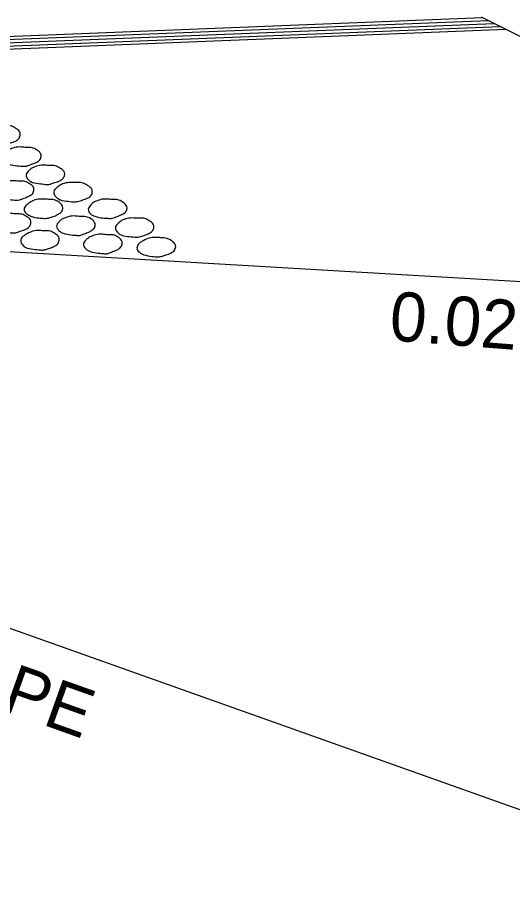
# Model space of a CAD drawing. Extents: x 438659 to 573674, y 10724 to 98600.
# Drawn here: x 514843 to 516659, y 68148 to 71311 of the extents above; entities that cross this region are included whole.
import ezdxf

# ---------------------------------------------------------------- set-up
doc = ezdxf.new("R2010")
doc.units = 0
doc.layers.add('T_Vehicle Path Rt', color=7, linetype='Continuous')

msp = doc.modelspace()

# ---------------------------------------------------------------- linework, layer by layer
at = {"layer": 'T_Vehicle Path Rt'}
for p, q in [((497292.2, 70531), (516568.3, 71300)), ((497314.8, 70541.7), (516547.7, 71310.2)), ((520270.3, 69449), (516544.6, 71311.4)), ((497241.8, 70505.8), (516612.3, 71278.1)), ((497266.8, 70517.7), (516590.9, 71289)), ((497216.5, 70492.7), (516634.1, 71267.2)), ((514103.7, 70495.3), (518717.5, 70225)), ((512200.6, 70004), (517415.7, 68148.2))]:
    msp.add_line(p, q, dxfattribs=at)
for points in [[(514783.6, 70844.5), (514758.1, 70847.7), (514730.2, 70855.4), (514714.2, 70869.7), (514712, 70877), (514720.3, 70894), (514729.3, 70900.3), (514745, 70910.3), (514768.6, 70915.1), (514780.5, 70915.1), (514799.4, 70915.8), (514820.3, 70913.2), (514837.5, 70904.4), (514851.3, 70892.8), (514853.8, 70882.6), (514849.1, 70869), (514838.7, 70858.8), (514826.3, 70853.7), (514809.6, 70849.4), (514799.4, 70846.4), (514783.6, 70844.5)], [(514860.8, 70765.9), (514834.6, 70768.3), (514805.7, 70776.3), (514791.6, 70790.4), (514789, 70799.1), (514796.7, 70813.9), (514803.5, 70821.5), (514821.2, 70830.2), (514844.8, 70836), (514857.6, 70836), (514876.1, 70834.6), (514897.2, 70833.3), (514913.2, 70826.3), (514927.8, 70812.7), (514930.7, 70803.5), (514925.8, 70789.7), (514914.7, 70780.7), (514903.3, 70775.8), (514886.3, 70769.5), (514876.1, 70766.4), (514860.8, 70765.9)], [(514946.4, 70698.9), (514921, 70702.3), (514892.1, 70709.4), (514877.5, 70724.6), (514875.1, 70732.2), (514883.1, 70747.7), (514890.2, 70754.2), (514906.9, 70763.5), (514931.2, 70769.5), (514942.8, 70769.5), (514961.7, 70768.3), (514982.4, 70767.1), (514998.9, 70759.1), (515014.4, 70746.5), (515016.8, 70736.3), (515012, 70723.7), (515000.8, 70713.7), (514989.6, 70709.1), (514972.4, 70703.5), (514961.7, 70699.4), (514946.4, 70698.9)], [(514833.4, 70641.9), (514807.9, 70644.3), (514779.3, 70652.3), (514764.5, 70666.6), (514762.3, 70674.9), (514770.5, 70690.2), (514777.3, 70697.2), (514794.5, 70706.7), (514818.3, 70712.3), (514830.2, 70712.3), (514849.1, 70711), (514870.3, 70709.6), (514885.8, 70703), (514901.6, 70689.5), (514903.7, 70680.2), (514899.4, 70665.9), (514887.7, 70657.7), (514876.6, 70651.8), (514859.8, 70645.5), (514849.1, 70642.4), (514833.4, 70641.9)], [(515047.9, 70635.1), (515022.6, 70638), (514993.5, 70645.8), (514979, 70660.3), (514976.5, 70667.9), (514983.8, 70683.6), (514992.6, 70690.9), (515008.6, 70700.9), (515032.3, 70705.7), (515044.5, 70705.7), (515063.4, 70706.4), (515084, 70703.5), (515100.5, 70694.5), (515115.6, 70682.9), (515117.5, 70673.4), (515113.9, 70659.4), (515101.5, 70649.4), (515091.3, 70644.8), (515073.8, 70639.5), (515063.4, 70636.8), (515047.9, 70635.1)], [(514941.4, 70574.7), (514915.4, 70576.9), (514885.3, 70585.8), (514870.3, 70598.7), (514867.6, 70608.2), (514875.8, 70622.5), (514884.3, 70629.8), (514902, 70640), (514925.1, 70645.3), (514938, 70645.3), (514956.9, 70644.3), (514978, 70642.4), (514993.5, 70635.3), (515007.4, 70621.8), (515009.5, 70613), (515004.7, 70598.5), (514993.8, 70590.2), (514982.4, 70584.4), (514967.1, 70579), (514957.6, 70575.9), (514941.4, 70574.7)], [(515174.5, 70574.9), (515149.1, 70576.9), (515119.7, 70585.4), (515104.9, 70599.2), (515103, 70608.2), (515111.7, 70622.7), (515118, 70630.2), (515135.7, 70639.2), (515159, 70645.3), (515171.1, 70645.3), (515190.3, 70643.8), (515211.2, 70642.6), (515227, 70635.3), (515242.2, 70622), (515244.9, 70613), (515240.1, 70598.5), (515228.7, 70590.2), (515217.2, 70584.9), (515200.3, 70578.1), (515190.3, 70575.2), (515174.5, 70574.9)], [(514823.7, 70521.5), (514798.2, 70524.7), (514769.1, 70532.5), (514753.5, 70546.8), (514752.1, 70554.8), (514759.1, 70570.8), (514768.3, 70576.4), (514784.4, 70586.3), (514808.1, 70592.9), (514820.8, 70592.9), (514839.7, 70590.9), (514860.8, 70589.7), (514876.1, 70581.7), (514891.1, 70569.3), (514892.8, 70558.9), (514888.7, 70546.3), (514877.5, 70536.6), (514865.9, 70531.7), (514849.1, 70526.1), (514839.7, 70522.3), (514823.7, 70521.5)], [(515058.1, 70512.6), (515032.6, 70515.2), (515003.7, 70523.5), (514989.2, 70537.6), (514986.5, 70546.3), (514995, 70561.3), (515002, 70568.6), (515019, 70576.9), (515042.8, 70583.2), (515055.2, 70583.2), (515074.3, 70581.7), (515094.7, 70580.3), (515111.2, 70574.2), (515126, 70559.9), (515128.4, 70551.6), (515123.6, 70536.6), (515112.9, 70528.6), (515100.8, 70523), (515084, 70516.2), (515074.3, 70513), (515058.1, 70512.6)], [(515273.3, 70506), (515247.8, 70508.7), (515218.7, 70516), (515204.9, 70530.8), (515202.2, 70538.3), (515209.7, 70553.8), (515217, 70560.8), (515234.2, 70570.8), (515257.8, 70575.9), (515270.1, 70575.9), (515289.1, 70575.2), (515310.2, 70574.4), (515326, 70566.2), (515341, 70553.1), (515343.2, 70543.1), (515339.3, 70530.3), (515328.1, 70520.6), (515316.7, 70515.5), (515299, 70509.4), (515289.1, 70506.5), (515273.3, 70506)], [(514927.8, 70458.9), (514902, 70461.6), (514872.2, 70469.1), (514857.6, 70484.2), (514855.2, 70492.2), (514863.2, 70507.9), (514871.5, 70513.8), (514888.2, 70523.5), (514912.2, 70530), (514924.1, 70530), (514942.8, 70528.6), (514963.7, 70527.6), (514980.4, 70518.9), (514994.5, 70507), (514996.7, 70496.3), (514992.3, 70483.2), (514981.1, 70473.7), (514970, 70468.6), (514953.7, 70463.1), (514942.8, 70459.4), (514927.8, 70458.9)], [(515158.3, 70445.6), (515132.3, 70448.3), (515102.5, 70456.5), (515087.9, 70470.6), (515085.2, 70479.3), (515093, 70494.1), (515101, 70501.4), (515118.2, 70510.6), (515142.3, 70516.2), (515155.4, 70516.2), (515173.8, 70514.7), (515194.4, 70513.8), (515210.2, 70507), (515225.3, 70493.1), (515227, 70484.2), (515222.6, 70469.9), (515211.2, 70461.1), (515199.8, 70456), (515183.8, 70449.7), (515173.8, 70445.8), (515158.3, 70445.6)], [(515354.8, 70433.5), (515329.1, 70436.4), (515299, 70444.6), (515283.5, 70458.2), (515281.3, 70466.7), (515289.1, 70482.2), (515297.6, 70488.8), (515315.3, 70498.7), (515338.8, 70504.6), (515351.2, 70504.6), (515369.4, 70503.8), (515390.5, 70501.2), (515406.5, 70493.4), (515420.3, 70481), (515423.3, 70471.1), (515418.4, 70457.7), (515406.8, 70448.3), (515396.6, 70443.6), (515380.3, 70438.3), (515370.1, 70435.2), (515354.8, 70433.5)]]:
    msp.add_spline(points, degree=3, dxfattribs=at)

# ---------------------------------------------------------------- texts
for s, rotation, p in [("0.020'/'", 355.6232, (516203.1, 70128.5)), ('EXISTING SLOPE', 340.4108, (513204.2, 69336))]:
    msp.add_text(s, height=180, rotation=rotation, dxfattribs=at).set_placement(p)

doc.saveas('drawing.dxf')
